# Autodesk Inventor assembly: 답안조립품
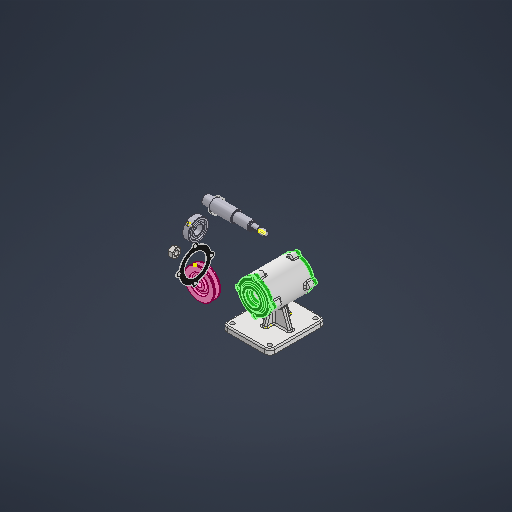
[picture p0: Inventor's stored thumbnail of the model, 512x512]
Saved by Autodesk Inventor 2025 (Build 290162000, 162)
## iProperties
Created: 2025-08
Part Number: 답안조립품
Document SubType Name: Weldment
Designer: infra012
Weld Material: Welded Aluminum-6061
Author: infra012
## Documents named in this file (12)
- C:\Users\infra012\Desktop\750806V1002\답안조립품.iam
- C:\Users\infra012\Desktop\750806V1002\본체.ipt
- C:\Users\infra012\Desktop\12345\공용부품_20250517_2\V-벨트풀리\V-벨트풀리.ipt
- C:\Users\infra012\Desktop\12345\공용부품_20250517_2\개스킷\개스킷.ipt
- C:\Users\infra012\Desktop\12345\공용부품_20250517_2\너트 M12 x 1.25\너트 M12 x 1.25.ipt
- C:\Users\infra012\Desktop\12345\공용부품_20250517_2\뒤커버\뒤커버.ipt
- C:\Users\infra012\Desktop\12345\공용부품_20250517_2\베어링 6204\베어링 6204.ipt
- C:\Users\infra012\Desktop\12345\공용부품_20250517_2\볼트 M4 x 12\볼트 M4 x 12.ipt
- C:\Users\infra012\Desktop\12345\공용부품_20250517_2\앞커버\앞커버.ipt
- C:\Users\infra012\Desktop\12345\공용부품_20250517_2\오일 실\오일 실.ipt
- C:\Users\infra012\Desktop\12345\공용부품_20250517_2\축\축.ipt
- C:\Users\infra012\Desktop\12345\공용부품_20250517_2\키 4 x 4\키 4 x 4.ipt
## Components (2 placed, 2 different names)
1. V-벨트풀리:1
2. 개스킷:1
